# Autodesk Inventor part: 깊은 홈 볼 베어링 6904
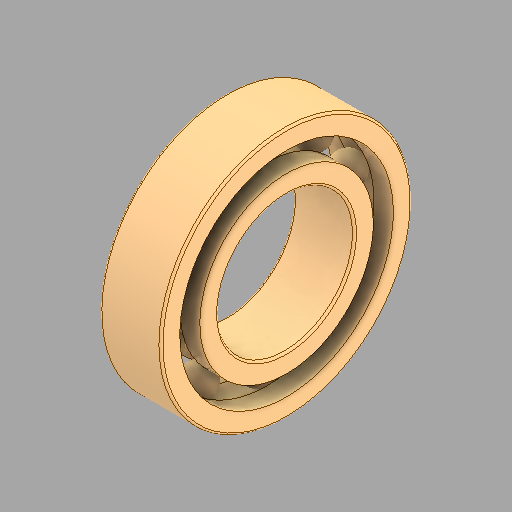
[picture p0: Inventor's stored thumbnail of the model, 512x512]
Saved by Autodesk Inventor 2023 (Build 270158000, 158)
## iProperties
Created: 2025-09
Part Number: 깊은 홈 볼 베어링 6904
Material: 강철, 연강
Description: 깊은 그루브 볼 베어링
Document SubType Name: Modeling
Designer: home
Density: 7.85 g/cm^3
Appearance: 기본값
Author: jhkim
Sending System: Autodesk Inventor 2026
Preprocessor: ST-DEVELOPER v20.1
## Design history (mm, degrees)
feature "Solid1"
feature "Solid1:1"
feature "Solid1:2"
feature "Solid1:3"
feature "Solid1:4"
feature "Solid1:5"
feature "Solid1:6"
feature "Solid1:7"
feature "Solid1:8"
feature "Solid1:9"
feature "Solid1:10"
feature "Solid1:11"
node "솔리드1"
node "솔리드2"
node "솔리드3"
node "솔리드4"
node "솔리드5"
node "솔리드6"
node "솔리드7"
node "솔리드8"
node "솔리드9"
node "솔리드10"
node "솔리드11"
node "솔리드12"
